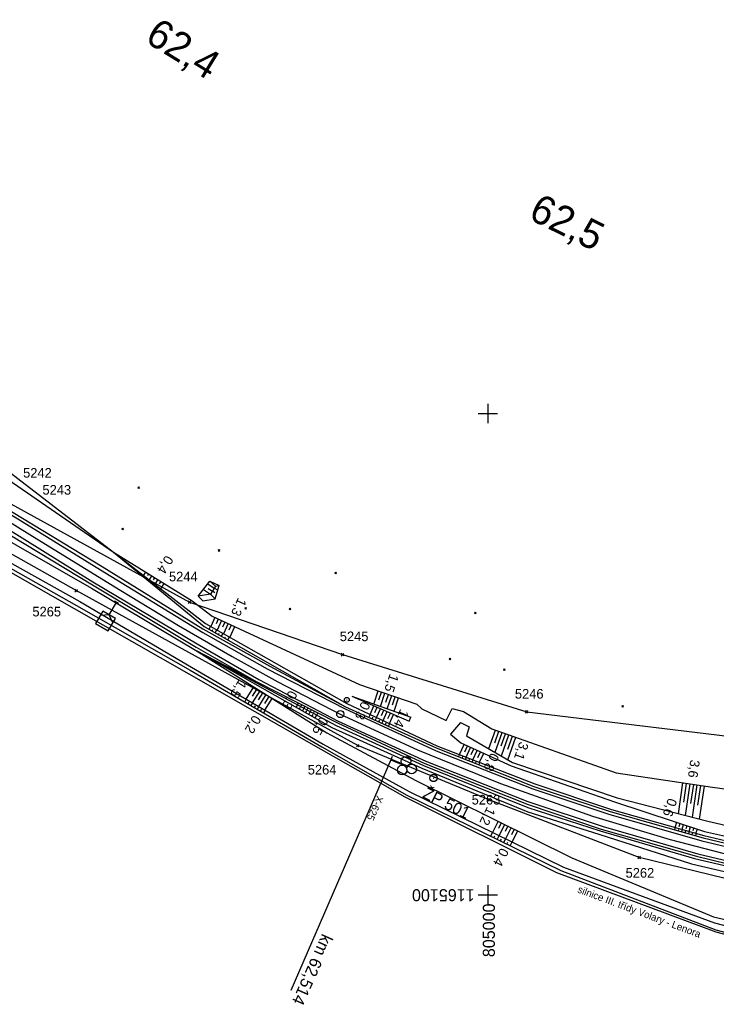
# Model space of a CAD drawing. Extents: x -805636 to -804553, y -1165340 to -1164656.
# Drawn here: x -805097.2 to -804952.6, y -1165124 to -1164918.2 of the extents above; entities that cross this region are included whole.
import ezdxf

# ---------------------------------------------------------------- set-up
doc = ezdxf.new("R2010")
doc.units = 0
for name, color, linetype in [('0381KM061-064P - Vrstva 1', 7, 'Continuous'), ('0381KM061-064P - Vrstva 4', 7, 'Continuous'), ('0381KM061-064P - Vrstva 48', 7, 'Continuous'), ('0381KM061-064P - Vrstva 49', 7, 'Continuous'), ('0381KM061-064P - Vrstva 51', 7, 'Continuous'), ('0381KM061-064P - Vrstva 7', 7, 'Continuous'), ('0381KM061-064P - Vrstva 8', 7, 'Continuous'), ('krizky_1000 - souradnice', 7, 'Continuous'), ('krizky_1000 - Vrstva 1', 7, 'Continuous'), ('szdc - hran DP', 7, 'Continuous'), ('szdc - szdc_cislo', 7, 'Continuous'), ('szdc - szdc_krizek', 7, 'Continuous'), ('vyt_sit - stávající', 7, 'Continuous')]:
    doc.layers.add(name, color=color, linetype=linetype)

msp = doc.modelspace()

# ---------------------------------------------------------------- linework, layer by layer
at = {"layer": '0381KM061-064P - Vrstva 1'}
for points in [[(-805131.47, -1165002.7), (-805117.01, -1165011.6), (-805094.55, -1165025.46), (-805076.19, -1165036.77)], [(-805076.19, -1165036.77), (-805064.24, -1165044.04), (-805053.13, -1165050.53)], [(-805053.13, -1165050.53), (-805043.64, -1165055.76), (-805030.64, -1165062.45), (-805014.61, -1165069.88), (-804997.39, -1165076.92), (-804978.26, -1165083.66), (-804962.13, -1165088.54), (-804947.73, -1165092.28), (-804936.17, -1165094.91), (-804922.95, -1165097.46), (-804911.85, -1165099.22)]]:
    msp.add_lwpolyline(points, dxfattribs=at)
at = {"layer": '0381KM061-064P - Vrstva 4'}
for points in [[(-805257.4, -1164945.18), (-805227.5, -1164957.9), (-805205.55, -1164967.2), (-805161.7, -1164987.26), (-805121.4, -1165011.84), (-805082.08, -1165035.58)], [(-805257.21, -1164944.39), (-805227.21, -1164957.06), (-805205.17, -1164966.48), (-805161.59, -1164986.72), (-805120.84, -1165010.88), (-805082.03, -1165034.98)], [(-805187.57, -1164970.92), (-805160.12, -1164984.24), (-805119.58, -1165008.37), (-805080.47, -1165032.5)], [(-805187.4, -1164970.45), (-805159.98, -1164983.82), (-805119.44, -1165007.96), (-805080.11, -1165031.8)], [(-805080.11, -1165031.8), (-805059.18, -1165044.72), (-805045.31, -1165052.51), (-805029.54, -1165060.96), (-805010.72, -1165069.47), (-804990.45, -1165077.48), (-804974.57, -1165082.73), (-804955.28, -1165088.2), (-804932.96, -1165093.51), (-804912.39, -1165097.1), (-804892.28, -1165099.85)], [(-805080.47, -1165032.5), (-805059.19, -1165045.48), (-805045.86, -1165053.03), (-805029.76, -1165061.31), (-805010.76, -1165070.1), (-804990.66, -1165078.03), (-804974.85, -1165083.28), (-804955.57, -1165088.82), (-804933.31, -1165094.09), (-804912.36, -1165097.73), (-804892.37, -1165100.24)], [(-805082.08, -1165035.58), (-805060.58, -1165048.58), (-805047.98, -1165055.77), (-805031.23, -1165064.28), (-805013.07, -1165072.73), (-804991.62, -1165081.24), (-804976.47, -1165086.37), (-804956.64, -1165091.96), (-804934.05, -1165097.54), (-804913.13, -1165101.06), (-804892.22, -1165103.81)], [(-805082.03, -1165034.98), (-805060.37, -1165047.85), (-805047.54, -1165055.28), (-805031.06, -1165063.92), (-805012.89, -1165072.24), (-804991.69, -1165080.62), (-804976.05, -1165085.82), (-804956.42, -1165091.49), (-804933.87, -1165096.82), (-804912.82, -1165100.43), (-804892.24, -1165103.28)]]:
    msp.add_lwpolyline(points, dxfattribs=at)
at = {"layer": '0381KM061-064P - Vrstva 48'}
for p, q in [((-805071.7, -1165033.78), (-805071.58, -1165033.63)), ((-805071.12, -1165032.94), (-805071.56, -1165033.64)), ((-805070.48, -1165033.33), (-805070.72, -1165033.72)), ((-805069.84, -1165033.72), (-805070.36, -1165034.57)), ((-805071.12, -1165034.26), (-805071.05, -1165034.17)), ((-805070.54, -1165034.73), (-805070.39, -1165034.55)), ((-805069.96, -1165035.21), (-805069.88, -1165035.11)), ((-805069.21, -1165034.12), (-805069.49, -1165034.57)), ((-805069.38, -1165035.68), (-805069.2, -1165035.47)), ((-805068.57, -1165034.51), (-805069.17, -1165035.49)), ((-805067.93, -1165034.91), (-805068.25, -1165035.43)), ((-805067.29, -1165035.3), (-805067.98, -1165036.41)), ((-805058.16, -1165035.39), (-805056.82, -1165036.27)), ((-805068.8, -1165036.16), (-805068.71, -1165036.04)), ((-805068.22, -1165036.63), (-805068.02, -1165036.38)), ((-805059.08, -1165036.56), (-805057.62, -1165037.51)), ((-805058.06, -1165036.34), (-805057.22, -1165036.89)), ((-805056.69, -1165037.24), (-805057.22, -1165036.89)), ((-805056.11, -1165036.74), (-805056.82, -1165036.27)), ((-805056.69, -1165042.41), (-805057.55, -1165044.27)), ((-805056.01, -1165042.72), (-805056.45, -1165043.68)), ((-805055.32, -1165043.04), (-805056.24, -1165045.01)), ((-805054.64, -1165043.35), (-805055.11, -1165044.37)), ((-805053.96, -1165043.67), (-805054.93, -1165045.76)), ((-805053.28, -1165043.99), (-805053.78, -1165045.05)), ((-805057.91, -1165044.8), (-805057.59, -1165044.25)), ((-805057.26, -1165045.18), (-805057.1, -1165044.9)), ((-805056.61, -1165045.55), (-805056.29, -1165044.99)), ((-805055.96, -1165045.92), (-805055.8, -1165045.64)), ((-805055.31, -1165046.29), (-805054.98, -1165045.72)), ((-805052.6, -1165044.3), (-805053.62, -1165046.5)), ((-805054.65, -1165046.66), (-805054.49, -1165046.38)), ((-805054, -1165047.03), (-805053.68, -1165046.46)), ((-805050.18, -1165059.36), (-805048.58, -1165056.81)), ((-805048.9, -1165058.73), (-805047.94, -1165057.21)), ((-805048.89, -1165060.12), (-805047.31, -1165057.61)), ((-805047.61, -1165059.5), (-805046.68, -1165058.01)), ((-805047.59, -1165060.88), (-805046.04, -1165058.41)), ((-805023.71, -1165060.37), (-805022.78, -1165057.65)), ((-805022.63, -1165059.53), (-805022.07, -1165057.89)), ((-805022.3, -1165060.87), (-805021.36, -1165058.14)), ((-805021.22, -1165060.02), (-805020.66, -1165058.38)), ((-805020.89, -1165061.37), (-805019.95, -1165058.62)), ((-805050.16, -1165059.38), (-805050.49, -1165059.95)), ((-805049.64, -1165059.98), (-805049.84, -1165060.32)), ((-805048.86, -1165060.13), (-805049.19, -1165060.7)), ((-805046.33, -1165060.28), (-805045.41, -1165058.81)), ((-805046.29, -1165061.63), (-805044.77, -1165059.21)), ((-805039.53, -1165060.53), (-805039.82, -1165061.03)), ((-805039.51, -1165060.54), (-805039.32, -1165060.17)), ((-805038.77, -1165060.74), (-805038.65, -1165060.51)), ((-805019.81, -1165060.52), (-805019.24, -1165058.87)), ((-805019.48, -1165061.86), (-805018.53, -1165059.11)), ((-805048.35, -1165060.74), (-805048.55, -1165061.08)), ((-805047.57, -1165060.89), (-805047.9, -1165061.46)), ((-805047.05, -1165061.49), (-805047.25, -1165061.83)), ((-805046.27, -1165061.65), (-805046.6, -1165062.21)), ((-805038.99, -1165061.09), (-805039.17, -1165061.4)), ((-805038.21, -1165061.24), (-805038.52, -1165061.77)), ((-805038.18, -1165061.25), (-805037.98, -1165060.85)), ((-805037.68, -1165061.81), (-805037.86, -1165062.14)), ((-805037.44, -1165061.44), (-805037.31, -1165061.19)), ((-805036.89, -1165061.95), (-805037.21, -1165062.51)), ((-805036.86, -1165061.96), (-805036.64, -1165061.53)), ((-805036.36, -1165062.53), (-805036.56, -1165062.88)), ((-805036.11, -1165062.14), (-805035.97, -1165061.87)), ((-805035.57, -1165062.66), (-805035.91, -1165063.25)), ((-805035.54, -1165062.67), (-805035.3, -1165062.21)), ((-805024.47, -1165062.52), (-805024.74, -1165063.13)), ((-805024.46, -1165062.53), (-805023.69, -1165060.75)), ((-805023.47, -1165062.13), (-805023, -1165061.05)), ((-805023.1, -1165063.16), (-805022.31, -1165061.35)), ((-805022.1, -1165062.75), (-805021.62, -1165061.65)), ((-805021.74, -1165063.8), (-805020.94, -1165061.95)), ((-805020.74, -1165063.37), (-805020.25, -1165062.25)), ((-805020.39, -1165064.44), (-805019.56, -1165062.55)), ((-805023.9, -1165063.08), (-805024.06, -1165063.44)), ((-805023.11, -1165063.16), (-805023.37, -1165063.75)), ((-805022.53, -1165063.71), (-805022.69, -1165064.05)), ((-805021.75, -1165063.79), (-805022.01, -1165064.36)), ((-805021.17, -1165064.34), (-805021.32, -1165064.67)), ((-805020.39, -1165064.43), (-805020.64, -1165064.98)), ((-804999.81, -1165069.65), (-804998.44, -1165065.79)), ((-804998.58, -1165068.43), (-804997.73, -1165066.04)), ((-804998.48, -1165070.41), (-804997.03, -1165066.29)), ((-804997.22, -1165069.09), (-804996.32, -1165066.54)), ((-804997.16, -1165071.17), (-804995.61, -1165066.79)), ((-805005.89, -1165070.86), (-805004.93, -1165068.76)), ((-804995.86, -1165069.75), (-804994.91, -1165067.04)), ((-804995.84, -1165071.94), (-804994.2, -1165067.29)), ((-805005.88, -1165070.86), (-805006.06, -1165071.31)), ((-805004.81, -1165070.31), (-805004.25, -1165069.07)), ((-805004.49, -1165071.4), (-805003.57, -1165069.38)), ((-805003.43, -1165070.88), (-805002.89, -1165069.69)), ((-805003.1, -1165071.95), (-805002.21, -1165070)), ((-805002.05, -1165071.46), (-805001.53, -1165070.31)), ((-805001.7, -1165072.49), (-805000.85, -1165070.62)), ((-805005.26, -1165071.31), (-805005.36, -1165071.58)), ((-805004.49, -1165071.41), (-805004.67, -1165071.86)), ((-805003.86, -1165071.86), (-805003.97, -1165072.13)), ((-805003.09, -1165071.95), (-805003.27, -1165072.41)), ((-805002.46, -1165072.41), (-805002.57, -1165072.68)), ((-805001.69, -1165072.5), (-805001.88, -1165072.96)), ((-804960.43, -1165083.16), (-804959.47, -1165076.75)), ((-804959.31, -1165080.75), (-804958.72, -1165076.86)), ((-804958.97, -1165083.54), (-804957.98, -1165076.97)), ((-804957.84, -1165081.07), (-804957.24, -1165077.09)), ((-804957.51, -1165083.92), (-804956.5, -1165077.2)), ((-804956.37, -1165081.39), (-804955.76, -1165077.31)), ((-804956.05, -1165084.29), (-804955.02, -1165077.42)), ((-804997.87, -1165084.72), (-804999.02, -1165087.05)), ((-804997.2, -1165085.05), (-804997.77, -1165086.21)), ((-804996.53, -1165085.38), (-804997.68, -1165087.71)), ((-804961.1, -1165086), (-804960.76, -1165084.96)), ((-804960.24, -1165085.8), (-804960.04, -1165085.2)), ((-804999.41, -1165087.84), (-804999.02, -1165087.05)), ((-804995.85, -1165085.71), (-804996.43, -1165086.88)), ((-804995.18, -1165086.05), (-804996.33, -1165088.36)), ((-804994.51, -1165086.38), (-804995.08, -1165087.54)), ((-804993.84, -1165086.71), (-804994.98, -1165089.03)), ((-804961.08, -1165086.01), (-804961.22, -1165086.52)), ((-804960.41, -1165086.42), (-804960.5, -1165086.72)), ((-804959.63, -1165086.42), (-804959.78, -1165086.93)), ((-804959.66, -1165086.41), (-804959.33, -1165085.43)), ((-804958.97, -1165086.82), (-804959.06, -1165087.13)), ((-804958.81, -1165086.23), (-804958.62, -1165085.67)), ((-804958.19, -1165086.82), (-804958.34, -1165087.33)), ((-804958.21, -1165086.82), (-804957.91, -1165085.9)), ((-804957.53, -1165087.23), (-804957.62, -1165087.54)), ((-804957.37, -1165086.67), (-804957.2, -1165086.14)), ((-804956.75, -1165087.23), (-804956.89, -1165087.75)), ((-804956.77, -1165087.22), (-804956.48, -1165086.37)), ((-804998.73, -1165088.17), (-804998.54, -1165087.77)), ((-804998.06, -1165088.5), (-804997.67, -1165087.71)), ((-804997.39, -1165088.83), (-804997.19, -1165088.43)), ((-804996.71, -1165089.16), (-804996.32, -1165088.37)), ((-804996.04, -1165089.49), (-804995.84, -1165089.09)), ((-804995.36, -1165089.82), (-804994.98, -1165089.03))]:
    msp.add_line(p, q, dxfattribs=at)
at = {"layer": '0381KM061-064P - Vrstva 49'}
for p, q in [((-805072.34, -1165015.61), (-805072.69, -1165015.26)), ((-805072.34, -1165015.26), (-805072.69, -1165015.61)), ((-805075.64, -1165024.19), (-805076, -1165023.84)), ((-805075.64, -1165023.84), (-805076, -1165024.19)), ((-805055.69, -1165028.65), (-805056.04, -1165028.29)), ((-805055.69, -1165028.29), (-805056.04, -1165028.65)), ((-805031.42, -1165033.3), (-805031.77, -1165032.95)), ((-805031.42, -1165032.95), (-805031.77, -1165033.3)), ((-805050.15, -1165040.65), (-805050.5, -1165040.3)), ((-805050.15, -1165040.3), (-805050.5, -1165040.65)), ((-805040.91, -1165040.77), (-805041.26, -1165040.42)), ((-805040.91, -1165040.42), (-805041.26, -1165040.77)), ((-805002.45, -1165041.64), (-805002.8, -1165041.28)), ((-805002.45, -1165041.28), (-805002.8, -1165041.64)), ((-805007.66, -1165051.16), (-805008.02, -1165050.81)), ((-805007.66, -1165050.81), (-805008.02, -1165051.16)), ((-804996.38, -1165053.38), (-804996.73, -1165053.03)), ((-804996.38, -1165053.03), (-804996.73, -1165053.38)), ((-804971.83, -1165061.04), (-804972.19, -1165060.69)), ((-804971.83, -1165060.69), (-804972.19, -1165061.04)), ((-805029.54, -1165060.96), (-805010.72, -1165069.47))]:
    msp.add_line(p, q, dxfattribs=at)
for points in [[(-805254.52, -1164927.32), (-805250.48, -1164933.58), (-805239.73, -1164938.85), (-805217.98, -1164949.5), (-805160.38, -1164977.95), (-805138.64, -1164988.6), (-805110.66, -1165003.53), (-805077.76, -1165028.83)], [(-805234.27, -1164967.17), (-805220.67, -1164970.52), (-805207.94, -1164974.16), (-805191.02, -1164980.42), (-805165.29, -1164994.07), (-805122, -1165019.23), (-805085.43, -1165039.91)], [(-805234.06, -1164966.19), (-805220.55, -1164969.15), (-805207.89, -1164972.65), (-805190.88, -1164979.53), (-805164.65, -1164993.41), (-805121.85, -1165018.34), (-805084.74, -1165039.06)], [(-805205.55, -1164967.2), (-805162.48, -1164988.88), (-805121.89, -1165013.64), (-805082.35, -1165036.29)], [(-805185.93, -1164967.81), (-805156.92, -1164981.59), (-805111.71, -1165005.38), (-805077.76, -1165028.83)], [(-805077.76, -1165028.83), (-805058.62, -1165043.66), (-805029.31, -1165060.25)], [(-805077.76, -1165028.83), (-805061.41, -1165038.93), (-805057.27, -1165042.14), (-805026.66, -1165056.32), (-805014.74, -1165060.42)], [(-805077.76, -1165028.83), (-805058.9, -1165044.24), (-805029.54, -1165060.96)], [(-805060.16, -1165037.96), (-805057.76, -1165034.87)], [(-805057.76, -1165034.87), (-805055.79, -1165035.72)], [(-805056.55, -1165035.87), (-805057.76, -1165034.87)], [(-805056.55, -1165035.87), (-805057.62, -1165037.51)], [(-805056.65, -1165038.5), (-805055.79, -1165035.72)], [(-805056.55, -1165035.87), (-805055.79, -1165035.72)], [(-805082.35, -1165036.29), (-805060.73, -1165049.17)], [(-805057.62, -1165037.51), (-805060.16, -1165037.96)], [(-805060.16, -1165037.96), (-805059.18, -1165038.9), (-805056.65, -1165038.5)], [(-805057.62, -1165037.51), (-805056.65, -1165038.5)], [(-805085.43, -1165039.91), (-805061.8, -1165053.37), (-805034.45, -1165069.27), (-805016.82, -1165079.3), (-804984.87, -1165094.97), (-804952.63, -1165107.29), (-804923.66, -1165115.02), (-804890.91, -1165119.51), (-804860.93, -1165120.87), (-804821.85, -1165122.9), (-804805.33, -1165123.27)], [(-805084.74, -1165039.06), (-805061.55, -1165052.74), (-805034.17, -1165068.7), (-805016.31, -1165078.58), (-804984.31, -1165094.26), (-804952.92, -1165105.84), (-804923.4, -1165113.55), (-804890.69, -1165118.62), (-804860.79, -1165119.97), (-804821.99, -1165121.8), (-804804.98, -1165122.47)], [(-805060.73, -1165049.17), (-805031.5, -1165064.84), (-805013.36, -1165073.14), (-804991.7, -1165081.91), (-804976.67, -1165086.76), (-804957.06, -1165092.46), (-804934.14, -1165097.81), (-804913.12, -1165101.52), (-804892.37, -1165104.14)], [(-805060.73, -1165049.17), (-805032.39, -1165065.25)], [(-805060.73, -1165049.17), (-805033.41, -1165066.35)], [(-805060.73, -1165049.17), (-805047.98, -1165055.77), (-805031.23, -1165064.28), (-805013.07, -1165072.73), (-804991.62, -1165081.24), (-804976.47, -1165086.37), (-804956.64, -1165091.96), (-804934.05, -1165097.54), (-804913.13, -1165101.06), (-804892.22, -1165103.81), (-804860.51, -1165107.09), (-804841.9, -1165109.22), (-804820.58, -1165111.74), (-804811.31, -1165113.56)], [(-805029.31, -1165060.25), (-805010.57, -1165069.03), (-804990.26, -1165076.95), (-804974.29, -1165082.29), (-804955.12, -1165087.69)], [(-805028.22, -1165058.77), (-805015.98, -1165063.1)], [(-805028.22, -1165058.77), (-805016.34, -1165063.96)], [(-805014.74, -1165060.42), (-805013.72, -1165061.35), (-805008.65, -1165063.79), (-805007.41, -1165061.32), (-805005.07, -1165061.94), (-804999.18, -1165065.52), (-804973.34, -1165074.67), (-804953.36, -1165077.67), (-804930.03, -1165080.86)], [(-805016.34, -1165063.96), (-805015.98, -1165063.1)], [(-805005.66, -1165064.21), (-805007.76, -1165066.63), (-805005.59, -1165068.46), (-804995.17, -1165073.22)], [(-805005.66, -1165064.21), (-805003.85, -1165065.08), (-805004.43, -1165066.97), (-804994.86, -1165072.51)], [(-805033.41, -1165066.35), (-805014.98, -1165076.25), (-804982.53, -1165092.31), (-804953.12, -1165104.6), (-804922.96, -1165111.59), (-804890.43, -1165117.32), (-804859.92, -1165117.39), (-804821.94, -1165119.94), (-804804.42, -1165121.15)], [(-805032.39, -1165065.25), (-805013.72, -1165073.73), (-804991.69, -1165082.79), (-804976.92, -1165087.4), (-804957.71, -1165093.59), (-804934.8, -1165098.93), (-804913.68, -1165102.56), (-804892.44, -1165105.41)], [(-805010.72, -1165069.47), (-804990.45, -1165077.48), (-804974.57, -1165082.73), (-804955.28, -1165088.2), (-804932.96, -1165093.51), (-804912.39, -1165097.1), (-804892.28, -1165099.85), (-804859.81, -1165103.25), (-804840.34, -1165105.46), (-804819.52, -1165107.92), (-804802.69, -1165109.64), (-804799.68, -1165110)], [(-804994.86, -1165072.51), (-804973.16, -1165079.86), (-804954.29, -1165084.75), (-804932.5, -1165089.79), (-804920.22, -1165090.5), (-804911.77, -1165084.22), (-804893.29, -1165083.05), (-804876.57, -1165085.04), (-804853.44, -1165091.21), (-804839.72, -1165094.63), (-804814.35, -1165098.18)], [(-804995.17, -1165073.22), (-804973.67, -1165080.7), (-804954.98, -1165086.86), (-804932.57, -1165091.85), (-804911.87, -1165094.85)], [(-804955.12, -1165087.69), (-804932.8, -1165092.95), (-804911.98, -1165096.48), (-804892.31, -1165098.96)]]:
    msp.add_lwpolyline(points, dxfattribs=at)
at = {"layer": '0381KM061-064P - Vrstva 51'}
for points in [[(-805234.38, -1164968.09), (-805220.73, -1164971.11), (-805207.78, -1164974.89), (-805191.18, -1164980.95), (-805165.61, -1164994.58), (-805122.14, -1165019.85), (-805085.93, -1165040.55)], [(-805085.93, -1165040.55), (-805062.08, -1165054.12), (-805034.69, -1165069.73), (-805017.21, -1165079.65), (-804985.71, -1165095.39), (-804952.66, -1165107.75), (-804923.93, -1165115.31), (-804890.75, -1165120.1), (-804861.18, -1165121.85), (-804821.92, -1165123.67), (-804805.64, -1165124)]]:
    msp.add_lwpolyline(points, dxfattribs=at)
at = {"layer": '0381KM061-064P - Vrstva 7'}
for p, q in [((-805078.64, -1165041.84), (-805077.12, -1165039.26)), ((-805076.69, -1165039.51), (-805077.56, -1165039)), ((-805029.33, -1165059.48), (-805029.24, -1165059.53))]:
    msp.add_line(p, q, dxfattribs=at)
for points in [[(-805078.64, -1165041.84), (-805079.94, -1165041.08), (-805081.46, -1165043.67), (-805078.87, -1165045.19), (-805077.35, -1165042.6), (-805078.64, -1165041.84)], [(-805077.86, -1165043.47), (-805078.64, -1165041.84), (-805080.45, -1165041.95)]]:
    msp.add_lwpolyline(points, dxfattribs=at)
for centre, radius in [((-805029.29, -1165059.51), 0.5), ((-805030.64, -1165062.45), 0.75)]:
    msp.add_circle(centre, radius, dxfattribs=at)
at = {"layer": '0381KM061-064P - Vrstva 8'}
for p, q in [((-805020.14, -1165071.99), (-805040.91, -1165119.94)), ((-805019.84, -1165071.3), (-805020.44, -1165072.67)), ((-805020.14, -1165071.99), (-805017.39, -1165073.18))]:
    msp.add_line(p, q, dxfattribs=at)
for centre in [(-805016.99, -1165072.26), (-805015.83, -1165073.86), (-805017.79, -1165074.1)]:
    msp.add_circle(centre, 1, dxfattribs=at)
at = {"layer": 'krizky_1000 - Vrstva 1'}
for points in [[(-805000, -1164998), (-805000, -1165002)], [(-805002, -1165000), (-804998, -1165000)], [(-805000, -1165098), (-805000, -1165102)], [(-805002, -1165100), (-804998, -1165100)]]:
    msp.add_lwpolyline(points, dxfattribs=at)
at = {"layer": 'szdc - hran DP'}
for p, q in [((-805100.45, -1165018.04), (-805061.96, -1165039.19)), ((-805085.48, -1165036.81), (-805115.56, -1165019.91)), ((-805027.03, -1165069.02), (-805085.48, -1165036.81)), ((-805061.96, -1165039.19), (-805030.17, -1165050.11)), ((-805030.17, -1165050.11), (-804991.93, -1165061.99)), ((-804991.93, -1165061.99), (-804883.1, -1165075.15)), ((-804999.74, -1165080.26), (-805027.03, -1165069.02)), ((-804968.55, -1165092.26), (-804999.74, -1165080.26)), ((-804934.32, -1165100.62), (-804968.55, -1165092.26))]:
    msp.add_line(p, q, dxfattribs=at)
at = {"layer": 'szdc - szdc_krizek'}
for p, q in [((-805085.21, -1165037.07), (-805085.75, -1165036.54)), ((-805085.75, -1165037.07), (-805085.21, -1165036.54)), ((-805061.7, -1165039.46), (-805062.23, -1165038.93)), ((-805062.23, -1165039.46), (-805061.7, -1165038.93)), ((-805029.91, -1165050.38), (-805030.44, -1165049.84)), ((-805030.44, -1165050.38), (-805029.91, -1165049.84)), ((-804991.67, -1165062.26), (-804992.2, -1165061.73)), ((-804992.2, -1165062.26), (-804991.67, -1165061.73)), ((-805026.77, -1165069.28), (-805027.3, -1165068.76)), ((-805027.3, -1165069.28), (-805026.77, -1165068.76)), ((-804999.47, -1165080.53), (-805000.01, -1165080)), ((-805000.01, -1165080.53), (-804999.47, -1165080)), ((-804968.29, -1165092.53), (-804968.82, -1165092)), ((-804968.82, -1165092.53), (-804968.29, -1165092))]:
    msp.add_line(p, q, dxfattribs=at)
at = {"layer": 'vyt_sit - stávající'}
msp.add_line((-805011.33, -1165075.72), (-805011.24, -1165075.78), dxfattribs=at)
msp.add_circle((-805011.29, -1165075.75), 0.756, dxfattribs=at)

# ---------------------------------------------------------------- texts
at = {"layer": '0381KM061-064P - Vrstva 48'}
for s, rotation, p in [('0,4', 238.304, (-805066.88, -1165029.32)), ('1,3', 245.1485, (-805051.84, -1165038.14)), ('1,5', 251.0215, (-805020.34, -1165053.96)), ('1,5', 237.8283, (-805051.65, -1165055.14)), ('0,3', 245.683, (-805041.29, -1165057.41)), ('0,3', 245.683, (-805026.16, -1165059.68)), ('1,4', 246.405, (-805018.15, -1165061.28)), ('0,2', 239.8249, (-805048.7, -1165062.53)), ('0,5', 240.4291, (-805034.77, -1165062.85)), ('3,1', 250.5147, (-804993.36, -1165068.06)), ('0,8', 245.4289, (-804999.39, -1165070.38)), ('3,6', 261.4565, (-804957.92, -1165071.85)), ('0,6', 251.7483, (-804962.54, -1165079.81)), ('1,2', 243.6728, (-805000.13, -1165081.62)), ('0,4', 243.8879, (-804997.36, -1165090.12))]:
    msp.add_text(s, height=2, rotation=rotation, dxfattribs=at).set_placement(p)
at = {"layer": '0381KM061-064P - Vrstva 51'}
msp.add_text('silnice III. třídy Volary - Lenora', height=1.5, rotation=339.5082, dxfattribs=at).set_placement((-804981.49, -1165099.49))
at = {"layer": '0381KM061-064P - Vrstva 7'}
for s, rotation, p in [('62,4', 328.3477, (-805071.45, -1164922.62)), ('62,5', 333.6639, (-804991.8, -1164959.45))]:
    msp.add_text(s, height=6, rotation=rotation, dxfattribs=at).set_placement(p)
at = {"layer": '0381KM061-064P - Vrstva 8'}
for s, height, rotation, p in [('X-625', 1.5, 246.0395, (-805023.02, -1165079.26)), ('km 62,514', 2.5, 245.9676, (-805034.38, -1165107.96))]:
    msp.add_text(s, height=height, rotation=rotation, dxfattribs=at).set_placement(p)
at = {"layer": 'krizky_1000 - souradnice'}
for s, rotation, p in [('1165100', 180, (-805002.74, -1165098.85)), ('805000', 90, (-804998.54, -1165112.98))]:
    msp.add_text(s, height=2.5, rotation=rotation, dxfattribs=at).set_placement(p)
at = {"layer": 'szdc - szdc_cislo'}
for s, p in [('5242', (-805096.52, -1165013.33)), ('5243', (-805092.5, -1165016.86)), ('5244', (-805066.22, -1165034.89)), ('5265', (-805094.59, -1165042.17)), ('5245', (-805030.75, -1165047.31)), ('5246', (-804994.38, -1165059.25)), ('5264', (-805037.4, -1165075.02)), ('5263', (-805003.36, -1165081.26)), ('5262', (-804971.39, -1165096.46))]:
    msp.add_text(s, height=2, dxfattribs=at).set_placement(p)
at = {"layer": 'vyt_sit - stávající'}
msp.add_text('ŽP 501', height=2.4, rotation=333.5611, dxfattribs=at).set_placement((-805013.74, -1165079.72))

doc.saveas('drawing.dxf')
